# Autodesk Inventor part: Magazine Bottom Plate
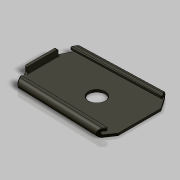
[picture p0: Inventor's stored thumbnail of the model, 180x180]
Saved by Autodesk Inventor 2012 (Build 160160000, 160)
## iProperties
Company: MH Vaaben Teknik
Created: 2011-12
Part Number: Magazine Bottom Plate
Material: Steel, Mild
Document SubType Name: Modeling
Designer: Michael Høgh
Density: 7.86 g/cm^3
Project: Steen MK II
Engineer: MH Vaaben Teknik
Mass: 9.54347 g
Surface Area: 25.8022 cm^2
Volume: 1.21418 cm^3
Author: Michael Høgh
Title: Magazine Bottom Plate
Keywords: Sten MK II Magazine
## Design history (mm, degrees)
sketch "Sketch1"
  geometry: L1 (12.183, 13.7)-(12.183, -13.7); L2 (-20.317, -12.7)-(-20.317, 12.7); L3 (12.183, 13.7)-(-20.317, 12.7); L4 (12.183, -13.7)-(-20.317, -12.7); L5 (-24.251, 0)-(23.824, 0); L6 (15.683, 8.5)-(15.683, -8.5); L7 (12.183, 13.7)-(15.683, 8.5); L8 (15.683, -8.5)-(12.183, -13.7); L9 (-23.817, 6)-(-23.817, -6); L10 (-20.317, 12.7)-(-23.817, 6); L11 (-23.817, -6)-(-20.317, -12.7); 3 further points
  constraints: 22 end point, 2 parallel, 2 perpendicular, 1 horizontal alignment, 1 midpoint, 1 vertical alignment
  dimensions: "d0" = 27.4 distance of L1.start L1.end; "d1" = 25.4 distance of L2.start L2.end; "d2" = 12.7 distance from line of L2.end L5; "d3" = 0 distance from line of point (0, 0) L5; "d4" = 32.5 distance between parallel lines of L1 L2; "d5" = 3.5 distance between parallel lines of L6 L1; "d7" = 3.5 distance between parallel lines of L2 L9; "d8" = 12 distance of L9.start L9.end; "d10" = 6 distance from line of L9.start L5; "d11" = 5.2 vertical distance of L6.start L1.start; "d12" = 5.2 vertical distance of L6.end L1.end; "d41" = 17 distance of L6.start L6.end
extrude "Extrusion1" new body sketch "Sketch1" distance "d14" = 1; taper "d15" = 0 deg
sketch "Sketch2"
  geometry: L1 (15.683, 8.5)-(15.683, -8.5) reference; C1 r 3.25 at (-1.317, 0); 1 further point
  constraints: 1 centre point
  dimensions: "d16" = 6.5 diameter of C1; "d17" = 17 distance from line of L1 C1.centre
extrude "Extrusion2" cut sketch "Sketch2" stored distance "d18" = 1; taper "d19" = 0 deg
sketch "Sketch6"
  geometry: L1 (-20.317, 12.7)-(12.183, 13.7) reference; L2 (12.183, -13.7)-(-20.317, -12.7) reference; L3 (-20.317, -12.7)-(12.183, -13.7); L4 (12.183, -13.7)-(12.214, -12.7); L5 (12.214, -12.7)-(-20.848, -11.683); L6 (12.183, 13.7)-(-20.317, 12.7); L7 (-20.317, 12.7)-(-20.286, 11.7); L8 (-20.286, 11.7)-(12.843, 12.72); L9 (-20.317, 12.7)-(-20.848, 11.683); L10 (-20.317, 12.7)-(-23.817, 6) reference; L11 (-20.286, 11.7)-(-20.848, 11.683); L12 (12.183, 13.7)-(12.843, 12.72); L13 (15.683, 8.5)-(12.183, 13.7) reference; L14 (12.183, -13.7)-(12.843, -12.72); L15 (12.183, -13.7)-(15.683, -8.5) reference; L16 (12.214, -12.7)-(12.843, -12.72); L17 (-20.317, -12.7)-(-20.848, -11.683); L18 (-23.817, -6)-(-20.317, -12.7) reference; L19 (15.683, -8.5)-(12.183, -13.7) reference; L20 (-20.317, -12.7)-(-23.817, -6) reference; 1 further point
  constraints: 24 end point, 4 point on line, 2 collinear, 2 parallel, 2 perpendicular
  dimensions: "d26" = 1 distance of L4.end L2.start; "d27" = 1 distance of L7.end L1.start
extrude "Extrusion5" join sketch "Sketch6" distance "d30" = 1.2; taper "d31" = 0 deg
sketch "Sketch7"
  geometry: L1 (12.843, -12.72)-(12.183, -13.7) reference; L2 (-20.317, -12.7)-(-20.848, -11.683) reference; L3 (12.183, -13.7)-(-20.317, -12.7) reference; L4 (-20.848, -11.683)-(12.843, -12.72); L5 (12.843, -12.72)-(12.905, -10.721); L6 (12.905, -10.721)-(-20.786, -9.684); L7 (-20.786, -9.684)-(-20.848, -11.683); L8 (-20.848, -11.683)-(12.843, -12.72) reference; L9 (-20.317, -12.7)-(-21.91, -9.65); L10 (-20.317, -12.7)-(12.183, -13.7); L11 (12.183, -13.7)-(14.163, -10.759); L12 (12.905, -10.721)-(14.163, -10.759); L13 (-20.786, -9.684)-(-21.91, -9.65); L14 (-20.848, -11.683)-(-23.817, -6) reference; 1 further point
  constraints: 18 end point, 4 collinear, 4 parallel, 1 perpendicular, 1 point on line
  dimensions: "d32" = 2 distance of L5.end L1.start
extrude "Extrusion6" join sketch "Sketch7" distance "d33" = 1; taper "d34" = 0 deg
sketch "Sketch8"
  geometry: L1 (-20.848, 11.683)-(-20.317, 12.7) reference; L2 (-20.317, 12.7)-(12.183, 13.7) reference; L3 (-20.317, 12.7)-(12.183, 13.7); L4 (12.183, 13.7)-(12.276, 10.701); L5 (12.276, 10.701)-(-20.224, 9.701); L6 (-20.224, 9.701)-(-20.317, 12.7); L7 (-20.317, 12.7)-(-21.91, 9.65); L8 (-20.224, 9.701)-(-21.91, 9.65); L9 (12.183, 13.7)-(14.163, 10.759); L10 (15.683, 8.5)-(12.183, 13.7) reference; L11 (12.276, 10.701)-(14.163, 10.759); 2 further points
  constraints: 16 end point, 3 collinear, 2 parallel, 2 perpendicular, 1 point on line
  dimensions: "d35" = 3 distance of L2.end L4.end
extrude "Extrusion7" join sketch "Sketch8" distance "d36" = 1; taper "d37" = 0 deg
sketch "Sketch9"
  geometry: L1 (-23.817, 6)-(-22.817, 6); L2 (-22.817, 6)-(-22.817, -6); L3 (-22.817, -6)-(-23.817, -6); L4 (-23.817, -6)-(-23.817, 6); 1 further point
  constraints: 8 end point, 2 parallel, 1 horizontal, 1 perpendicular
  dimensions: "d38" = 1 distance of L2.end L3.end
extrude "Extrusion8" join sketch "Sketch9" distance "d39" = 2.5; taper "d40" = 0 deg
fillet "Fillet1" dims "d42" = 1.6
fillet "Fillet2" dims "d43" = 0.6
fillet "Fillet3" dims "d44" = 0.6
fillet "Fillet4" dims "d45" = 0.4
fillet "Fillet5" dims "d46" = 0.4
fillet "Fillet6" dims "d47" = 0.4
fillet "Fillet7" dims "d48" = 0.2
fillet "Fillet8" dims "d49" = 1
chamfer "Chamfer1" distance "d50" = 0.1; stored, may be unused: second distance "d51" = 2, angle "d52" = 45 deg
chamfer "Chamfer2" distance "d53" = 0.1; stored, may be unused: second distance "d54" = 2, angle "d55" = 45 deg
body "Solid1"
